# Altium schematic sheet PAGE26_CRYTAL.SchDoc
size 431 x 304 mm; SheetNumber: 29; SheetTotal: 28
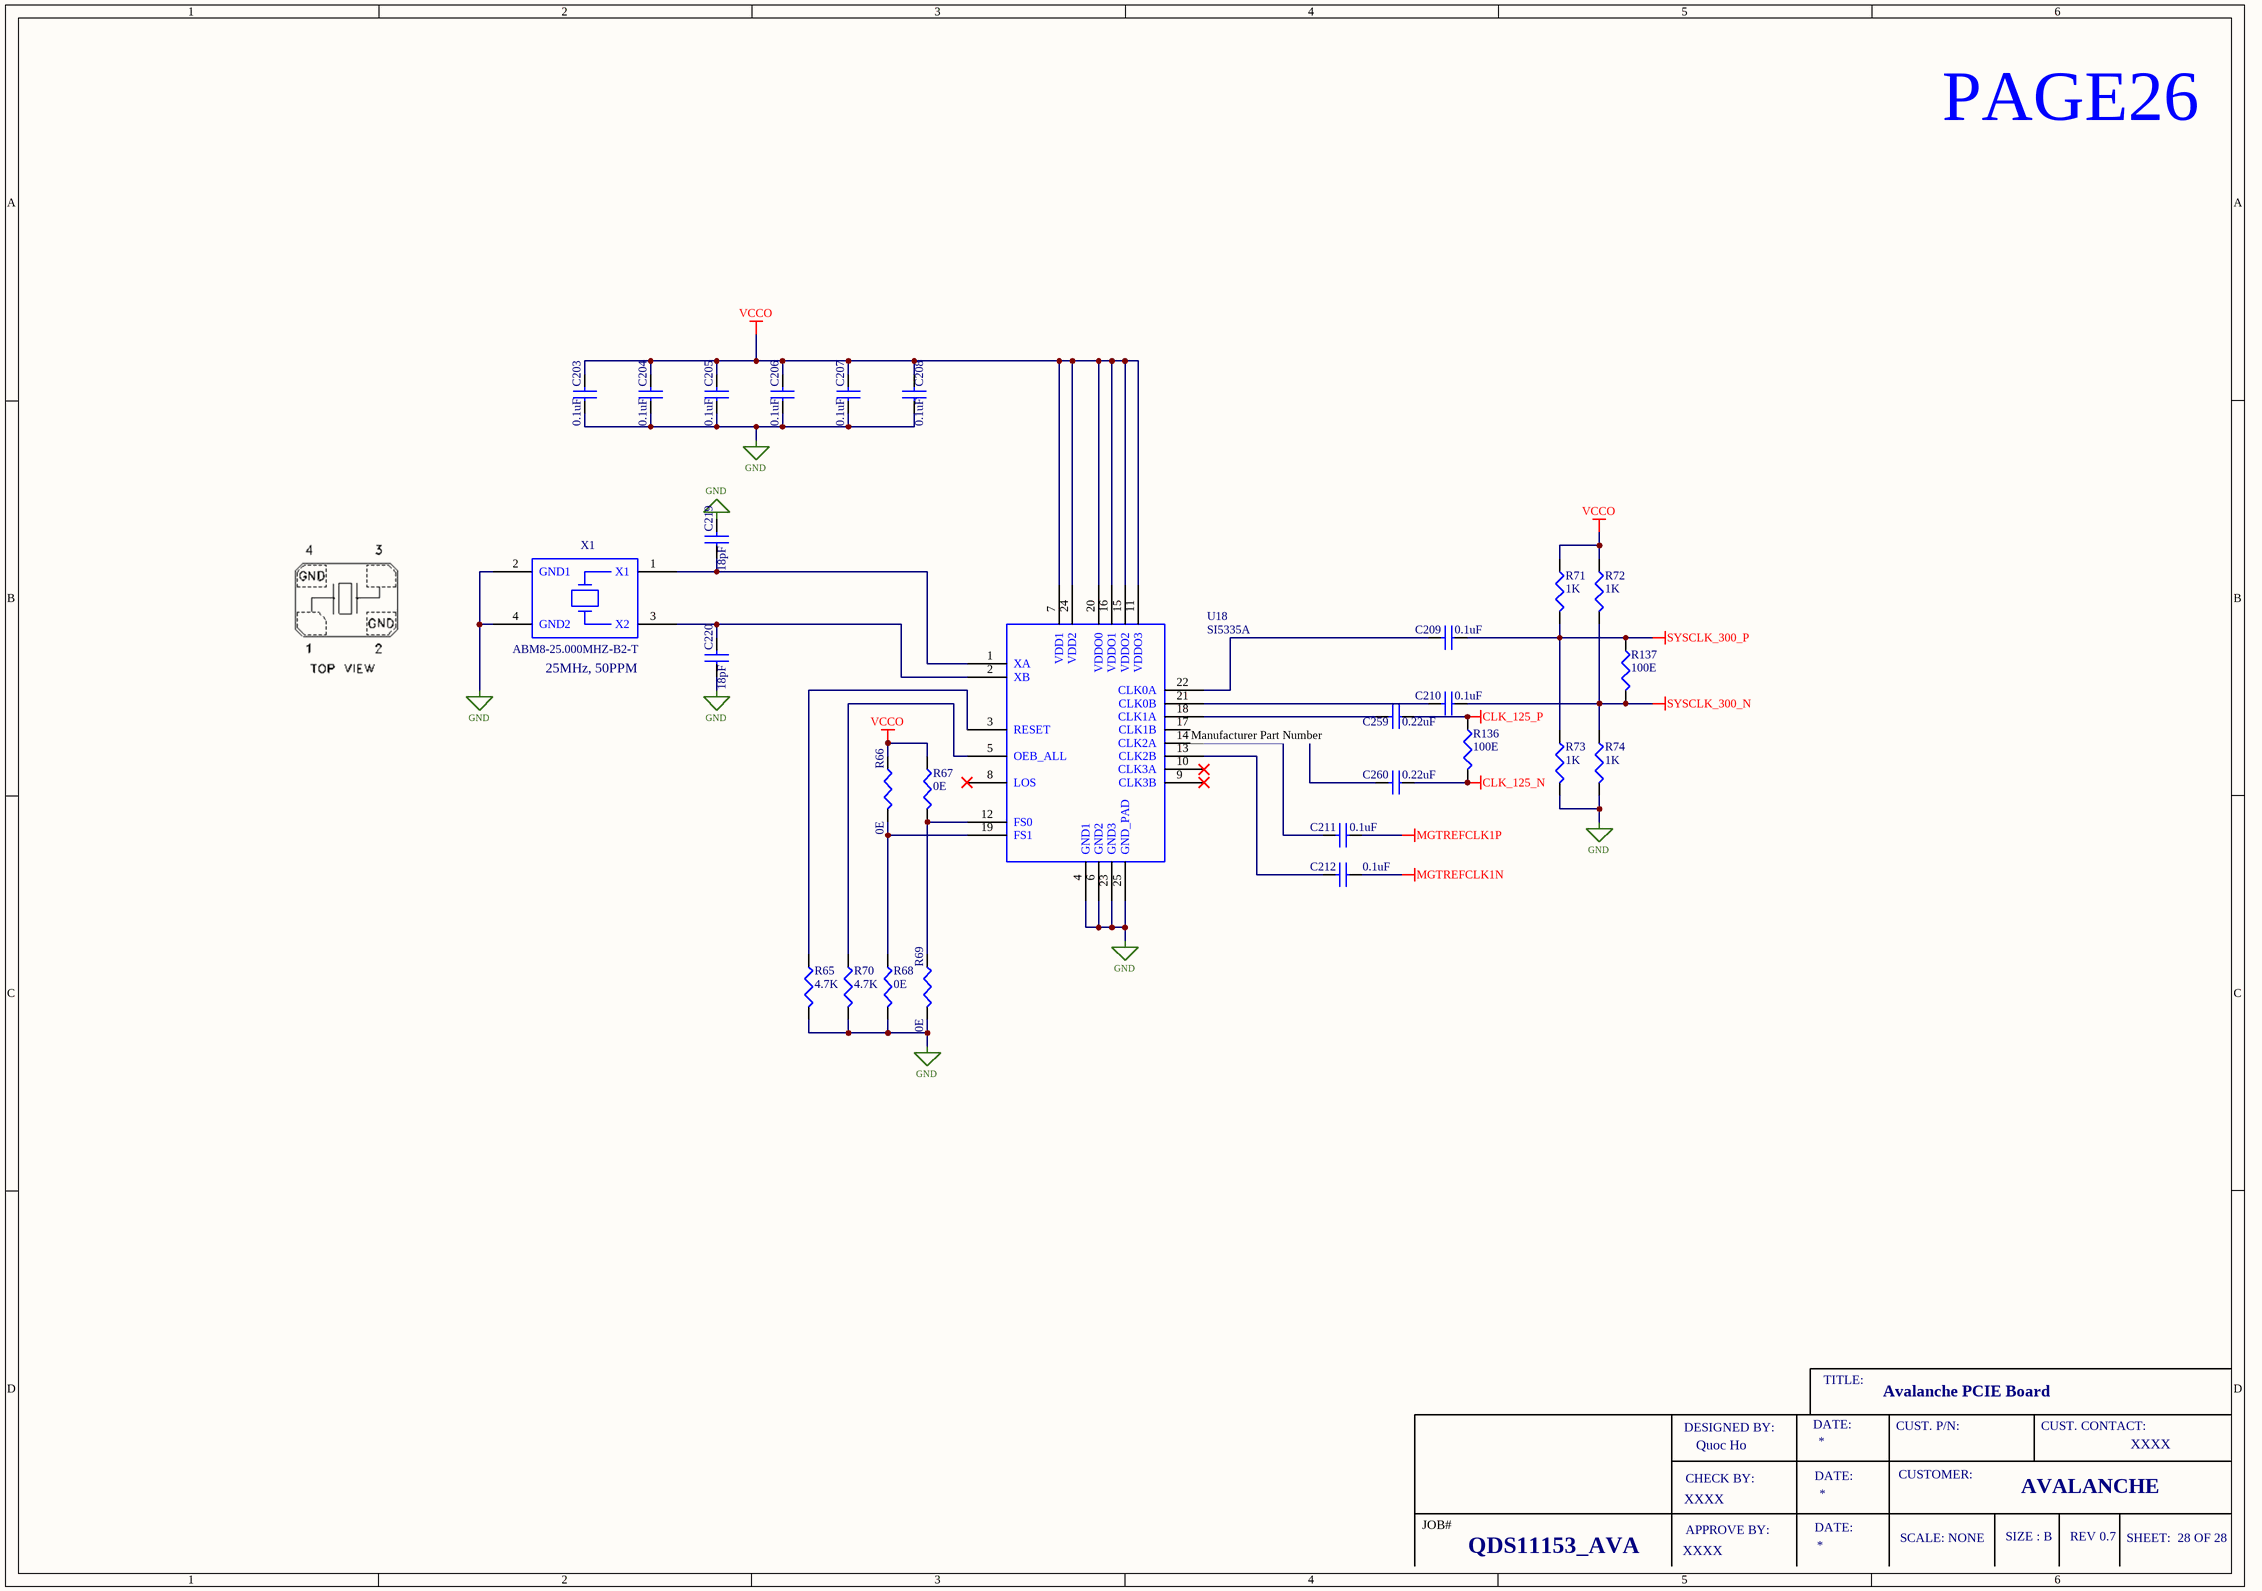
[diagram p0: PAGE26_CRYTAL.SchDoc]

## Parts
C203  0.1uF  [CN_0402]
C204  0.1uF  [CN_0402]
C205  0.1uF  [CN_0402]
C206  0.1uF  [CN_0402]
C207  0.1uF  [CN_0402]
C208  0.1uF  [CN_0402]
C209  0.1uF  [CN_0402]
C210  0.1uF  [CN_0402]
C211  0.1uF  [CN_0402]
C212  0.1uF  [CN_0402]
C219  18pF  [CN_0402]
C220  18pF  [CN_0402]
C259  0.22uF  [CN_0402]
C260  0.22uF  [CN_0402]
R65  4.7K  [RN_0402]
R66  0E  [RN_0402]
R67  0E  [RN_0402]
R68  0E  [RN_0402]
R69  0E  [RN_0402]
R70  4.7K  [RN_0402]
R71  1K  [RN_0402]
R72  1K  [RN_0402]
R73  1K  [RN_0402]
R74  1K  [RN_0402]
R136  100E  [RN_0402]
R137  100E  [RN_0402]
U18  SI5335A  [SI5335A - QFN24]
X1  ABM8-25.000MHZ-B2-T  [AMB8]

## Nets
CLK_125_N: C260.1 R136.2
CLK_125_P: C259.1 R136.1
GND: C203.1 C204.1 C205.1 C206.1 C207.1 C208.1 C219.2 C220.1 R65.2 R68.2 R69.2 R70.2 R73.2 R74.2 U18.4(GND1) U18.6(GND2) U18.23(GND3) U18.25(GND_PAD) X1.2(GND1) X1.4(GND2)
MGTREFCLK1N: C212.1
MGTREFCLK1P: C211.1
SYSCLK_300_N: C210.1 R72.2 R74.1 R137.2
SYSCLK_300_P: C209.1 R71.2 R73.1 R137.1
VCCO: C203.2 C204.2 C205.2 C206.2 C207.2 C208.2 R66.1 R67.1 R71.1 R72.1 U18.7(VDD1) U18.11(VDDO3) U18.15(VDDO2) U18.16(VDDO1) U18.20(VDDO0) U18.24(VDD2)
NetC209_2: C209.2 U18.22(CLK0A)
NetC210_2: C210.2 U18.21(CLK0B)
NetC211_2: C211.2 U18.14(CLK2A)
NetC212_2: C212.2 U18.13(CLK2B)
NetC219_1: C219.1 U18.1(XA) X1.1(X1)
NetC220_2: C220.2 U18.2(XB) X1.3(X2)
NetC259_2: C259.2 U18.18(CLK1A)
NetC260_2: C260.2 U18.17(CLK1B)
NetR65_1: R65.1 U18.3(RESET)
NetR66_2: R66.2 R68.1 U18.19(FS1)
NetR67_2: R67.2 R69.1 U18.12(FS0)
NetR70_1: R70.1 U18.5(OEB_ALL)

Not connected (* = marked no-connect by the designer): U18 8(LOS)* 9(CLK3B)* 10(CLK3A)*

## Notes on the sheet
- PAGE26
- (near X1) 25MHz, 50PPM
- (near U18) Manufacturer Part Number
- TITLE:
- Avalanche PCIE Board
- DESIGNED BY:
- CHECK BY:
- Quoc Ho
- DATE:
- CUST. P/N:
- CUSTOMER:
- CUST. CONTACT:
- XXXX
- JOB#
- APPROVE BY:
- SCALE: NONE
- SIZE : B
- AVALANCHE
- REV 0.7
- SHEET:  28 OF 28
- QDS11153_AVA

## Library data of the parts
C203-C205 C208 C211 C212 = CAP: CAP CER 0.1UF 50V X7R 0402; Manufacturer: Murata Electronics; Manufacturer Part Number: GCM155R71H104KE02J
C206 C207 C209 C210 = CAP: CAP CER 0.1UF 50V X7R 0402; Manufacturer Part Number: GCM155R71H104KE02J; Manufacturer: Murata Electronics
C219 C220 = CAP: CAP CER 18PF 50V C0G/NP0 0402; Manufacturer Part Number: GJM1555C1H180GB01D; Manufacturer: Murata Electronics
C259 C260 = CAP: CAP CER 0.22UF 50V X5R 0402; Manufacturer Part Number: GRM155R61H224KE01W; Manufacturer: Murata Electronics
R65 R70 = RES: RES 4.7K OHM 1% 1/16W 0402; Manufacturer Part Number: RC0402FR-134K7L; Manufacturer: YAGEO
R66-R69 = RES: RES 0 OHM JUMPER 1/16W 0402; Manufacturer Part Number: RC0402FR-070RL; Manufacturer: YAGEO
R71-R74 = RES: RES 1K OHM 1% 1/16W 0402; Manufacturer Part Number: RC0402FR-131KL; Manufacturer: YAGEO
R136 R137 = RES: RES 100 OHM 1% 1/16W 0402; Manufacturer Part Number: RC0402FR-07100RL; Manufacturer: YAGEO
U18 = SI5335A: IC CLOCK GENERATOR 24QFN; Manufacturer Part Number: SI5335A-B02436-GM; Manufacturer: Skyworks Solutions Inc.
X1 = CRYSTAL: CRYSTAL 25.0000MHZ 18PF SMD; Manufacturer: Abracon LLC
